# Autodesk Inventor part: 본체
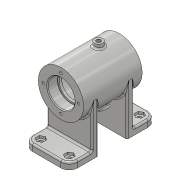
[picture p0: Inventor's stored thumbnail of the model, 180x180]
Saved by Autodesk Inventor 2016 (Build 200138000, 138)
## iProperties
Created: 2017-02
Part Number: 본체
Material: 알루미늄 6061
Document SubType Name: Modeling
Designer: H
Density: 2.7 g/cm^3
Appearance: 알루미늄 - 평지
Mass: 353.37 g
Surface Area: 426.421 cm^2
Volume: 130.878 cm^3
Author: H
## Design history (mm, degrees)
sketch "스케치1"
  geometry: L1 (-27, -52)-(27, -52); L2 (27, 52)-(-27, 52); L3 (-27, -52)-(27, 52); L4 (27, -52)-(-27, 52); L5 (-27, -17)-(27, -17); L6 (27, 17)-(-27, 17); L7 (-27, -17)-(27, 17); L8 (27, -17)-(-27, 17); L9 (27, -52)-(27, -17); L10 (27, 17)-(27, 52); L11 (-27, 52)-(-27, 17); L12 (-27, -17)-(-27, -52); 1 further point
  constraints: 24 end point, 6 parallel, 4 midpoint, 2 horizontal, 2 perpendicular
  dimensions: "d4" = 34 distance between parallel lines of L5 L6; "d5" = 54 distance between parallel lines of L10 L11; "d6" = 17 distance from line of point (0, 0) L6; "d7" = 52 vertical distance of point (0, 0) L2.end; "d8" = 27 distance from line of L10 point (0, 0)
extrude "돌출1" new body sketch "스케치1" distance "d9" = 8; taper "d10" = 0 deg
sketch "스케치2"
  geometry: L1 (52, 0)-(17, 0) reference; L2 (17, 0)-(17, 8) reference; L3 (52, 8)-(17, 8) reference; L4 (52, 0)-(52, 8) reference; L5 (-17, 0)-(-52, 0) reference; L6 (-52, 0)-(-52, 8) reference; L7 (-17, 8)-(-52, 8) reference; L8 (-17, 0)-(-17, 8) reference; L9 (17, 0)-(25, 0); L10 (25, 0)-(25, 60); L11 (25, 60)-(17, 60); L12 (17, 60)-(17, 0); L13 (-17, 0)-(-25, 0); L14 (-25, 0)-(-25, 60); L15 (-25, 60)-(-17, 60); L16 (-17, 60)-(-17, 0); 1 further point
  constraints: 16 end point, 4 parallel, 2 horizontal, 2 perpendicular
  dimensions: "d11" = 8 distance of L11.end L10.end; "d12" = 60 distance of L9.end L10.end; "d13" = 8 distance of L14.end L15.end; "d14" = 60 distance of L13.end L14.end
extrude "돌출2" join sketch "스케치2" stored distance "d15" = 54; taper "d16" = 0 deg
sketch "스케치3"
  geometry: L1 (27, 60)-(-27, 60) reference; C1 r 27 at (0, 60); 2 further points
  constraints: 1 centre point, 1 coincident, 1 midpoint
  dimensions: "d17" = 54 diameter of C1
extrude "돌출3" join sketch "스케치3" stored distance "d18" = 70; taper "d19" = 0 deg
sketch "스케치4"
  geometry: L1 (17, 60)-(25, 60) reference; L2 (17, 60)-(17, 60) reference; L3 (25, 60)-(17, 60) reference; L4 (25, 60)-(25, 60) reference; L5 (-25, 60)-(-25, 60) reference; L6 (-17, 60)-(-25, 60) reference; L7 (-17, 60)-(-17, 60) reference; L8 (-25, 60)-(-17, 60) reference; L9 (-35, 87)-(-35, 33) reference; L10 (35, 33)-(35, 87) reference; L11 (15, 82)-(10, 82); L12 (10, 82)-(10, 92); L13 (10, 92)-(15, 92); L14 (15, 92)-(15, 82); 1 further point
  constraints: 8 end point, 2 parallel, 1 horizontal, 1 perpendicular
  dimensions: "d20" = 5 distance of L12.end L13.end; "d21" = 5 distance from line of L10.end L13; "d22" = 25 distance from line of L12 L10.end; "d23" = 10 distance of L13.end L11.start
revolve "회전1" sketch "스케치4" stored, may be unused: angle "d24" = 90 deg
sketch "스케치5"
  geometry: L1 (0, 60)-(-16.339, 34.84); L2 (0, 60)-(0, 33); L3 (-21.371, 38.108)-(-17.014, 44.817); L4 (-21.371, 38.108)-(-16.339, 34.84); L5 (-17.014, 44.817)-(-11.982, 41.549); 1 further point
  constraints: 10 end point, 2 perpendicular, 1 point on line, 1 vertical, 1 vertical alignment, 1 other
  dimensions: "d25" = 30 distance of L1.start L1.end; "d26" = 33 deg angle of L1 L2; "d27" = 6 distance between parallel lines of L1 L3; "d29" = 8 distance of L3.start L3.end
revolve "회전2" sketch "스케치5" stored, may be unused: angle "d30" = 90 deg
sketch "스케치6"
  geometry: L1 (35, 33)-(35, 87) reference; L2 (-35, 87)-(-35, 33) reference; L3 (35, 60)-(-35, 60); L4 (35, 60)-(35, 76); L5 (35, 76)-(23, 76); L6 (23, 76)-(23, 74); L7 (23, 74)-(20, 74); L8 (20, 74)-(20, 82); L9 (20, 82)-(-20, 82); L10 (-20, 82)-(-20, 74); L11 (-20, 74)-(-23, 74); L12 (-23, 74)-(-23, 76); L13 (-23, 76)-(-35, 76); L14 (-35, 76)-(-35, 60); 1 further point
  constraints: 24 end point, 9 perpendicular, 2 midpoint, 2 point on line, 1 vertical
  dimensions: "d31" = 16 distance of L3.start L4.end; "d32" = 12 distance of L4.end L5.end; "d33" = 3 distance of L6.end L7.end; "d34" = 40 distance of L8.end L9.end; "d35" = 3 distance of L10.end L11.end; "d36" = 32 diameter of L13 L3; "d37" = 28 diameter of L11 L3; "d38" = 28 diameter of L7 L3; "d39" = 44 diameter of L9 L3
revolve "회전3" sketch "스케치6" stored, may be unused: angle "d40" = 90 deg
sketch "스케치7"
  geometry: C1 r 16 at (0, 0) reference; C2 r 27 at (0, 0) reference; 2 further points
  dimensions: "d41" = 21 distance of C1.centre point (0, -21); "d42" = 0 horizontal distance of C1.centre point (0, -21)
hole "구멍1" sketch "스케치7" at (0, -21) diameter "d43" = 3.242; stored, may be unused: countersink angle "d47" = 90 deg, drill point angle "d49" = 118 deg; dims "d44" = 8, "d45" = 4, "d46" = 2, "d48" = 10
sketch "스케치8"
  geometry: C1 r 5 at (0, 0) reference; 2 further points
  constraints: 1 coincident
hole "구멍2" sketch "스케치8" at (0, 0) diameter "d53" = 5.188; stored, may be unused: countersink angle "d57" = 90 deg, drill point angle "d59" = 118 deg; dims "d54" = 15, "d55" = 4, "d56" = 2, "d58" = 19
sketch "스케치9"
  geometry: C1 r 6 at (0, 0) reference; 2 further points
  constraints: 1 coincident
hole "구멍3" sketch "스케치9" at (0, 0) diameter "d60" = 5.188; stored, may be unused: countersink angle "d64" = 90 deg, drill point angle "d66" = 118 deg; dims "d61" = 15, "d62" = 4, "d63" = 2, "d65" = 19
sketch "스케치10"
  geometry: L1 (17, 47.196)-(21.5, 44.598); L2 (21.5, 44.598)-(21.5, 39.402); L3 (21.5, 39.402)-(17, 36.804); L4 (17, 36.804)-(12.5, 39.402); L5 (12.5, 39.402)-(12.5, 44.598); L6 (12.5, 44.598)-(17, 47.196); L7 (27, 52)-(-27, 52) reference; C1 r 4.5 at (17, 42); 2 further points
  constraints: 12 end point, 1 centre point, 1 coincident, 1 tangent, 13 other
  dimensions: "d67" = 9 diameter of C1; "d68" = 90 deg angle of L2 L7; "d69" = 42 vertical distance of point (17, 42) point (0, 0); "d70" = 17 horizontal distance of point (17, 42) point (0, 0)
extrude "돌출4" cut sketch "스케치10" distance "d71" = 3; taper "d72" = 0 deg
sketch "스케치11"
  geometry: C1 r 2.5 at (17, 42); 1 further point
  constraints: 1 centre point
  dimensions: "d73" = 5 diameter of C1; "d74" = 17 horizontal distance of point (0, 0) C1.centre; "d75" = 42 vertical distance of C1.centre point (0, 0)
extrude "돌출5" cut sketch "스케치11" stored distance "d76" = 3; taper "d77" = 0 deg
fillet "모깎기1" dims "d84" = 10
chamfer "모따기1" distance "d85" = 1; stored, may be unused: second distance "d86" = 2, angle "d87" = 45 deg
fillet "모깎기2" dims "d88" = 0.3
fillet "모깎기3" dims "d89" = 2
fillet "모깎기4" dims "d90" = 2
fillet "모깎기5" dims "d91" = 2
node "작업 평면1"
sketch "스케치12"
  geometry: L1 (-35, 87)-(-35, 33) reference; 2 further points
  constraints: 1 other
  dimensions: "d93" = 35 distance from line of point (0, 60) L1; "d94" = 27 vertical distance of point (0, 60) L1.start
feature "엠보싱1" sketch "스케치12" dims "d95" = 0.5, "d96" = 0
fillet "모깎기6" dims "d97" = 3
node "솔리드1"
pattern_circular "원형 패턴1" dims angle "d51" = 360 deg
mirror "대칭1"
pattern_linear "직사각형 패턴1" dims "d80" = 84, "d83" = 34
node "투영된 루프1"
node "투영된 루프2"
node "투영된 루프3"
node "투영된 루프4"
node "투영된 루프5"
other parameters: "d92" = -75
